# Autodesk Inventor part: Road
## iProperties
Created: 2007-12
Part Number: Road
Document SubType Name: Modeling
Designer: UJA2299
Density: 1 g/cm^3
Author: UJA2299
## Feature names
1. 押し出し1 [Extrusion]
